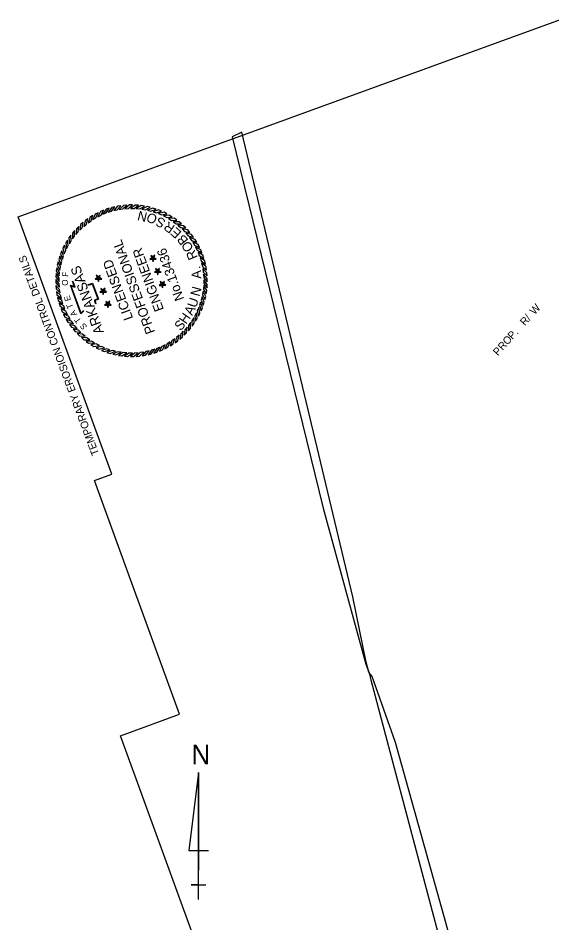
# Model space of a CAD drawing. Extents: x 986289 to 987754, y 1871116 to 1872971.
# Drawn here: x 986289 to 986709, y 1872081 to 1872793 of the extents above; entities that cross this region are included whole.
import ezdxf

# ---------------------------------------------------------------- set-up
doc = ezdxf.new("R2010")
doc.units = 0
for name, color, linetype in [('1', 7, 'Continuous'), ('63', 7, 'Continuous'), ('G-ANNO-SYMB', 7, 'Continuous'), ('NO PLOT', 7, 'Continuous'), ('R_Draft', 7, 'Continuous')]:
    doc.layers.add(name, color=color, linetype=linetype)

msp = doc.modelspace()

# ---------------------------------------------------------------- linework, layer by layer
at = {"layer": '63'}
for p, q in [((986430.69, 1872199.39), (986422.99, 1872137.85)), ((986430.69, 1872099.39), (986430.69, 1872199.39)), ((986430.69, 1872199.39), (986430.69, 1872122.46)), ((986422.99, 1872137.85), (986438.38, 1872137.85)), ((986430.69, 1872099.39), (986430.69, 1872122.46)), ((986430.69, 1872110.93), (986424.92, 1872110.93)), ((986424.92, 1872110.93), (986436.46, 1872110.93)), ((986430.69, 1872099.39), (986430.69, 1872110.93))]:
    msp.add_line(p, q, dxfattribs=at)
at = {"layer": 'G-ANNO-SYMB'}
for points in [[(986351.63, 1872639.84), (986349.35, 1872638.66), (986347.56, 1872634.45), (986349.94, 1872635.87)], [(986355.91, 1872641.74), (986353.54, 1872640.74), (986351.43, 1872636.69), (986353.92, 1872637.91)], [(986360.33, 1872643.29), (986357.89, 1872642.49), (986355.47, 1872638.61), (986358.04, 1872639.64)], [(986364.85, 1872644.5), (986362.36, 1872643.88), (986359.64, 1872640.21), (986362.29, 1872641.03)], [(986369.46, 1872645.34), (986366.93, 1872644.92), (986363.93, 1872641.47), (986366.63, 1872642.09)], [(986374.12, 1872645.82), (986371.57, 1872645.61), (986368.3, 1872642.4), (986371.05, 1872642.8)], [(986378.8, 1872645.94), (986376.24, 1872645.92), (986372.74, 1872642.98), (986375.5, 1872643.17)], [(986383.48, 1872645.68), (986380.92, 1872645.87), (986377.2, 1872643.21), (986379.97, 1872643.18)], [(986388.13, 1872645.06), (986385.59, 1872645.45), (986381.67, 1872643.09), (986384.43, 1872642.84)], [(986392.71, 1872644.08), (986390.21, 1872644.66), (986386.12, 1872642.62), (986388.85, 1872642.15)], [(986397.19, 1872642.74), (986394.75, 1872643.52), (986390.51, 1872641.8), (986393.2, 1872641.12)], [(986401.56, 1872641.05), (986399.19, 1872642.02), (986394.83, 1872640.64), (986397.45, 1872639.76)], [(986405.79, 1872639.03), (986403.5, 1872640.18), (986399.04, 1872639.15), (986401.59, 1872638.06)], [(986339.85, 1872632.23), (986337.91, 1872630.55), (986337.15, 1872626.04), (986339.14, 1872627.97)], [(986343.57, 1872635.07), (986341.5, 1872633.55), (986340.4, 1872629.11), (986342.53, 1872630.89)], [(986347.5, 1872637.62), (986345.33, 1872636.26), (986343.87, 1872631.92), (986346.14, 1872633.53)], [(986409.84, 1872636.68), (986407.65, 1872638), (986403.12, 1872637.33), (986405.58, 1872636.04)], [(986413.7, 1872634.02), (986411.61, 1872635.51), (986407.05, 1872635.19), (986409.4, 1872633.72)], [(986417.33, 1872631.06), (986415.37, 1872632.71), (986410.8, 1872632.75), (986413.02, 1872631.1)], [(986333.13, 1872625.71), (986331.48, 1872623.75), (986331.44, 1872619.17), (986333.09, 1872621.4)], [(986336.36, 1872629.1), (986334.56, 1872627.27), (986334.16, 1872622.72), (986335.99, 1872624.8)], [(986420.72, 1872627.83), (986418.9, 1872629.63), (986414.34, 1872630.03), (986416.43, 1872628.21)], [(986423.85, 1872624.34), (986422.17, 1872626.28), (986417.66, 1872627.04), (986419.6, 1872625.05)], [(986327.51, 1872618.22), (986326.19, 1872616.02), (986326.86, 1872611.5), (986328.15, 1872613.95)], [(986330.17, 1872622.07), (986328.68, 1872619.99), (986329, 1872615.43), (986330.48, 1872617.77)], [(986426.69, 1872620.62), (986425.17, 1872622.69), (986420.74, 1872623.79), (986422.51, 1872621.66)], [(986429.24, 1872616.69), (986427.88, 1872618.87), (986423.55, 1872620.32), (986425.15, 1872618.05)], [(986325.16, 1872614.17), (986324.01, 1872611.87), (986325.04, 1872607.42), (986326.13, 1872609.96)], [(986431.47, 1872612.57), (986430.29, 1872614.84), (986426.08, 1872616.63), (986427.5, 1872614.25)], [(986433.36, 1872608.28), (986432.37, 1872610.65), (986428.31, 1872612.76), (986429.54, 1872610.27)], [(986321.45, 1872605.57), (986320.67, 1872603.13), (986322.39, 1872598.89), (986323.07, 1872601.57)], [(986323.14, 1872609.94), (986322.17, 1872607.56), (986323.55, 1872603.2), (986324.44, 1872605.83)], [(986394.78, 1872604.03), (986393.78, 1872604.32), (986392.22, 1872603.1), (986394.2, 1872603.17)], [(986394.78, 1872604.03), (986394.74, 1872605.08), (986393.1, 1872606.18), (986393.78, 1872604.32)], [(986394.78, 1872604.03), (986394.2, 1872603.17), (986394.87, 1872601.31), (986395.42, 1872603.21)], [(986394.78, 1872604.03), (986395.76, 1872604.39), (986396.3, 1872606.3), (986394.74, 1872605.08)], [(986394.78, 1872604.03), (986395.42, 1872603.21), (986397.4, 1872603.28), (986395.76, 1872604.39)], [(986434.92, 1872603.86), (986434.11, 1872606.3), (986430.23, 1872608.72), (986431.26, 1872606.15)], [(986436.12, 1872599.34), (986435.51, 1872601.83), (986431.83, 1872604.55), (986432.66, 1872601.9)], [(986319.13, 1872596.5), (986318.74, 1872593.97), (986321.1, 1872590.05), (986321.35, 1872592.81)], [(986320.11, 1872601.08), (986319.53, 1872598.58), (986321.57, 1872594.49), (986322.04, 1872597.22)], [(986436.97, 1872594.73), (986436.55, 1872597.26), (986433.1, 1872600.26), (986433.71, 1872597.56)], [(986318.51, 1872591.86), (986318.32, 1872589.3), (986320.98, 1872585.58), (986321.01, 1872588.35)], [(986351.85, 1872588.41), (986351.82, 1872589.45), (986350.17, 1872590.56), (986350.85, 1872588.7)], [(986351.85, 1872588.41), (986352.83, 1872588.77), (986353.38, 1872590.67), (986351.82, 1872589.45)], [(986398.51, 1872593.78), (986397.51, 1872594.07), (986395.95, 1872592.85), (986397.93, 1872592.92)], [(986398.51, 1872593.78), (986398.47, 1872594.82), (986396.83, 1872595.93), (986397.51, 1872594.07)], [(986398.51, 1872593.78), (986397.93, 1872592.92), (986398.61, 1872591.06), (986399.15, 1872592.96)], [(986398.51, 1872593.78), (986399.49, 1872594.14), (986400.04, 1872596.04), (986398.47, 1872594.82)], [(986398.51, 1872593.78), (986399.15, 1872592.96), (986401.13, 1872593.03), (986399.49, 1872594.14)], [(986437.45, 1872590.07), (986437.23, 1872592.63), (986434.02, 1872595.89), (986434.42, 1872593.14)], [(986437.56, 1872585.39), (986437.54, 1872587.95), (986434.6, 1872591.45), (986434.79, 1872588.69)], [(986318.25, 1872587.18), (986318.27, 1872584.62), (986321.21, 1872581.11), (986321.03, 1872583.88)], [(986318.37, 1872582.5), (986318.59, 1872579.94), (986321.79, 1872576.68), (986321.39, 1872579.42)], [(986351.85, 1872588.41), (986350.85, 1872588.7), (986349.29, 1872587.48), (986351.27, 1872587.55)], [(986351.85, 1872588.41), (986351.27, 1872587.55), (986351.95, 1872585.68), (986352.49, 1872587.59)], [(986351.85, 1872588.41), (986352.49, 1872587.59), (986354.47, 1872587.66), (986352.83, 1872588.77)], [(986402.24, 1872583.53), (986401.24, 1872583.82), (986399.68, 1872582.6), (986401.66, 1872582.67)], [(986402.24, 1872583.53), (986402.21, 1872584.57), (986400.56, 1872585.68), (986401.24, 1872583.82)], [(986402.24, 1872583.53), (986401.66, 1872582.67), (986402.34, 1872580.81), (986402.88, 1872582.71)], [(986402.24, 1872583.53), (986403.22, 1872583.89), (986403.77, 1872585.79), (986402.21, 1872584.57)], [(986402.24, 1872583.53), (986402.88, 1872582.71), (986404.86, 1872582.78), (986403.22, 1872583.89)], [(986436.68, 1872576.07), (986437.07, 1872578.6), (986434.71, 1872582.52), (986434.46, 1872579.76)], [(986437.31, 1872580.71), (986437.49, 1872583.27), (986434.83, 1872586.99), (986434.8, 1872584.22)], [(986318.85, 1872577.84), (986319.27, 1872575.31), (986322.72, 1872572.31), (986322.1, 1872575.01)], [(986355.58, 1872578.16), (986354.58, 1872578.45), (986353.02, 1872577.23), (986355, 1872577.3)], [(986355.58, 1872578.16), (986355.55, 1872579.2), (986353.9, 1872580.31), (986354.58, 1872578.45)], [(986355.58, 1872578.16), (986355, 1872577.3), (986355.68, 1872575.43), (986356.22, 1872577.34)], [(986355.58, 1872578.16), (986356.56, 1872578.51), (986357.11, 1872580.42), (986355.55, 1872579.2)], [(986355.58, 1872578.16), (986356.22, 1872577.34), (986358.2, 1872577.41), (986356.56, 1872578.51)], [(986435.7, 1872571.49), (986436.28, 1872573.98), (986434.24, 1872578.08), (986433.78, 1872575.34)], [(986319.69, 1872573.23), (986320.31, 1872570.74), (986323.98, 1872568.02), (986323.16, 1872570.67)], [(986320.9, 1872568.7), (986321.71, 1872566.27), (986325.58, 1872563.85), (986324.55, 1872566.42)], [(986359.31, 1872567.91), (986358.31, 1872568.19), (986356.75, 1872566.97), (986358.73, 1872567.04)], [(986359.31, 1872567.91), (986359.28, 1872568.95), (986357.64, 1872570.06), (986358.31, 1872568.19)], [(986359.31, 1872567.91), (986360.29, 1872568.26), (986360.84, 1872570.17), (986359.28, 1872568.95)], [(986359.31, 1872567.91), (986359.96, 1872567.09), (986361.94, 1872567.16), (986360.29, 1872568.26)], [(986432.68, 1872562.63), (986433.64, 1872565), (986432.27, 1872569.36), (986431.38, 1872566.74)], [(986434.36, 1872567), (986435.14, 1872569.44), (986433.43, 1872573.68), (986432.75, 1872570.99)], [(986322.45, 1872564.29), (986323.45, 1872561.92), (986327.5, 1872559.81), (986326.28, 1872562.29)], [(986359.31, 1872567.91), (986358.73, 1872567.04), (986359.41, 1872565.18), (986359.96, 1872567.09)], [(986428.3, 1872554.35), (986429.63, 1872556.55), (986428.95, 1872561.07), (986427.66, 1872558.61)], [(986430.65, 1872558.4), (986431.8, 1872560.7), (986430.77, 1872565.15), (986429.68, 1872562.6)], [(986324.35, 1872560), (986325.53, 1872557.72), (986329.74, 1872555.94), (986328.32, 1872558.32)], [(986326.58, 1872555.88), (986327.93, 1872553.7), (986332.27, 1872552.25), (986330.66, 1872554.51)], [(986425.64, 1872550.49), (986427.13, 1872552.58), (986426.82, 1872557.14), (986425.34, 1872554.8)], [(986329.12, 1872551.95), (986330.64, 1872549.88), (986335.08, 1872548.78), (986333.3, 1872550.9)], [(986331.96, 1872548.23), (986333.64, 1872546.29), (986338.15, 1872545.53), (986336.22, 1872547.51)], [(986419.45, 1872543.47), (986421.26, 1872545.29), (986421.65, 1872549.85), (986419.83, 1872547.76)], [(986422.68, 1872546.86), (986424.34, 1872548.82), (986424.38, 1872553.39), (986422.72, 1872551.17)], [(986335.09, 1872544.74), (986336.92, 1872542.94), (986341.47, 1872542.54), (986339.39, 1872544.36)], [(986338.48, 1872541.51), (986340.44, 1872539.85), (986345.02, 1872539.81), (986342.79, 1872541.47)], [(986408.31, 1872534.95), (986410.49, 1872536.31), (986411.94, 1872540.64), (986409.68, 1872539.04)], [(986412.24, 1872537.5), (986414.31, 1872539.02), (986415.42, 1872543.45), (986413.29, 1872541.68)], [(986415.97, 1872540.34), (986417.91, 1872542.02), (986418.66, 1872546.53), (986416.68, 1872544.59)], [(986342.12, 1872538.55), (986344.2, 1872537.06), (986348.76, 1872537.38), (986346.42, 1872538.85)], [(986345.97, 1872535.89), (986348.17, 1872534.56), (986352.69, 1872535.24), (986350.24, 1872536.53)], [(986350.03, 1872533.54), (986352.32, 1872532.39), (986356.77, 1872533.42), (986354.23, 1872534.51)], [(986354.25, 1872531.52), (986356.63, 1872530.55), (986360.99, 1872531.92), (986358.36, 1872532.81)], [(986390.96, 1872528.07), (986393.45, 1872528.68), (986396.17, 1872532.36), (986393.52, 1872531.54)], [(986395.49, 1872529.27), (986397.92, 1872530.08), (986400.34, 1872533.96), (986397.77, 1872532.93)], [(986399.91, 1872530.83), (986402.27, 1872531.83), (986404.38, 1872535.88), (986401.9, 1872534.65)], [(986404.19, 1872532.73), (986406.47, 1872533.9), (986408.25, 1872538.11), (986405.87, 1872536.69)], [(986358.62, 1872529.83), (986361.06, 1872529.05), (986365.3, 1872530.76), (986362.62, 1872531.44)], [(986363.11, 1872528.49), (986365.61, 1872527.91), (986369.7, 1872529.95), (986366.97, 1872530.41)], [(986367.69, 1872527.51), (986370.23, 1872527.12), (986374.14, 1872529.48), (986371.38, 1872529.73)], [(986372.33, 1872526.89), (986374.89, 1872526.7), (986378.61, 1872529.36), (986375.84, 1872529.39)], [(986377.01, 1872526.63), (986379.57, 1872526.65), (986383.08, 1872529.59), (986380.31, 1872529.4)], [(986381.69, 1872526.74), (986384.25, 1872526.96), (986387.51, 1872530.17), (986384.77, 1872529.77)], [(986386.35, 1872527.23), (986388.88, 1872527.64), (986391.88, 1872531.09), (986389.18, 1872530.48)]]:
    msp.add_lwpolyline(points, close=True, dxfattribs=at)
for points in [[(986340.49, 1872562.49), (986338.13, 1872560.16), (986329.89, 1872582.76), (986332.95, 1872581.74), (986332.37, 1872583.27), (986331.89, 1872584.54), (986331.56, 1872585.88)], [(986340.22, 1872562.76), (986338.29, 1872560.85), (986330.52, 1872582.15), (986333.59, 1872581.12), (986332.73, 1872583.4), (986332.25, 1872584.66), (986331.93, 1872585.97)], [(986343.31, 1872583.36), (986343.87, 1872583.02), (986344.54, 1872583.08), (986345.81, 1872583.39), (986347.03, 1872583.83), (986351.36, 1872571.93), (986349.61, 1872571.29), (986348.88, 1872571.02), (986348.93, 1872570.12), (986349.53, 1872568.46), (986349.28, 1872568.13)], [(986343.51, 1872583.68), (986343.96, 1872583.41), (986344.48, 1872583.46), (986345.69, 1872583.75), (986347.26, 1872584.32), (986351.85, 1872571.7), (986349.74, 1872570.93), (986349.27, 1872570.76), (986349.3, 1872570.19), (986349.96, 1872568.4), (986349.59, 1872567.9)]]:
    msp.add_lwpolyline(points, dxfattribs=at)
at = {"layer": 'NO PLOT'}
msp.add_lwpolyline([(986774.2, 1871115.6), (986369.23, 1872228.25), (986415.65, 1872245.15), (986348.68, 1872429.14), (986362.4, 1872434.13), (986288.69, 1872636.64), (986718.28, 1872792.99), (986821.23, 1872510.15), (986748.87, 1872483.82), (986894.23, 1872084.45), (986966.59, 1872110.78), (987064.47, 1871841.86), (987008.75, 1871821.58), (987125.95, 1871499.59), (987181.66, 1871519.87), (987263.93, 1871293.85)], close=True, dxfattribs=at)
msp.add_lwpolyline([(986774.2, 1871115.6), (986369.23, 1872228.25), (986415.65, 1872245.15), (986348.68, 1872429.14), (986362.4, 1872434.13), (986288.69, 1872636.64), (986718.28, 1872792.99), (986821.23, 1872510.15), (986748.87, 1872483.82), (986894.23, 1872084.45), (986966.59, 1872110.78), (987064.47, 1871841.86), (987008.75, 1871821.58), (987125.95, 1871499.59), (987181.66, 1871519.87), (987263.93, 1871293.85)], close=True, dxfattribs=at)
msp.add_lwpolyline([(986774.2, 1871115.6), (986369.23, 1872228.25), (986415.65, 1872245.15), (986348.68, 1872429.14), (986362.4, 1872434.13), (986288.69, 1872636.64), (986718.28, 1872792.99), (986821.23, 1872510.15), (986748.87, 1872483.82), (986894.23, 1872084.45), (986966.59, 1872110.78), (987064.47, 1871841.86), (987008.75, 1871821.58), (987125.95, 1871499.59), (987181.66, 1871519.87), (987263.93, 1871293.85)], close=True, dxfattribs=at)
msp.add_lwpolyline([(986774.2, 1871115.6), (986369.23, 1872228.25), (986415.65, 1872245.15), (986348.68, 1872429.14), (986362.4, 1872434.13), (986288.69, 1872636.64), (986718.28, 1872792.99), (986821.23, 1872510.15), (986748.87, 1872483.82), (986894.23, 1872084.45), (986966.59, 1872110.78), (987064.47, 1871841.86), (987008.75, 1871821.58), (987125.95, 1871499.59), (987181.66, 1871519.87), (987263.93, 1871293.85)], close=True, dxfattribs=at)
msp.add_lwpolyline([(986631.76, 1872057.72), (986585.54, 1872222.93), (986567.3, 1872274.81), (986564.8, 1872277.83), (986564.79, 1872277.85), (986564.71, 1872278.16), (986562.57, 1872286.23), (986552.01, 1872337.51), (986464.8, 1872703.09), (986457.01, 1872699.61), (986528.8, 1872407.27), (986562.36, 1872284.62), (986564.8, 1872277.83), (986564.8, 1872277.83), (986564.93, 1872277.37), (986566.25, 1872272.25), (986630.52, 1872029.89)], dxfattribs=at)

# ---------------------------------------------------------------- texts
at = {"layer": '1'}
msp.add_text('TEMPORARY EROSION CONTROL DETAILS', height=6, rotation=110.32307, dxfattribs=at).set_placement((986352.56, 1872450.06))
at = {"layer": '63'}
msp.add_text('N', height=15.38, rotation=360, dxfattribs=at).set_placement((986425.05, 1872205.8))
at = {"layer": 'G-ANNO-SYMB'}
for s, height, rotation, p in [('N', 7.5, 166.10067, (986390.86, 1872639.67)), ('O', 7.5, 154.77573, (986398.99, 1872637.09)), ('S', 7.5, 153.48784, (986405.43, 1872633.95)), ('R', 7.5, 145.65967, (986412.58, 1872629.21)), ('E', 7.5, 137.83149, (986417.86, 1872624.39)), ('PROFESSIONAL', 7.5, 110, (986396.58, 1872545.95)), ('B', 7.5, 128.88501, (986423, 1872618.2)), ('ENGINEER', 7.5, 110, (986403.48, 1872563.67)), ('No.13436', 7.47, 110, (986419.47, 1872572)), ('O', 7.5, 121.42961, (986427.07, 1872611.68)), ('R', 7.5, 113.22866, (986430.15, 1872604.63)), ('ARKANSAS', 7.747, 110, (986356.35, 1872545.85)), ('LICENSED', 7.5, 110, (986379.29, 1872556.76)), ('.', 7.5, 101.30002, (986432.4, 1872595.67)), ('F', 4.75, 85.36282, (986328.12, 1872589.27)), ('A', 7.5, 93.09908, (986432.87, 1872587.99)), ('O', 4.75, 91.2218, (986327.96, 1872582.4)), ('N', 7.5, 74.93262, (986431.29, 1872573.51)), ('E', 4.75, 106.67203, (986330.37, 1872571.02)), ('U', 7.5, 70.90262, (986428.63, 1872564.49)), ('T', 4.75, 111.47887, (986332.31, 1872565.26)), ('A', 4.75, 118.67877, (986335.29, 1872559.82)), ('H', 7.5, 55.61905, (986420.83, 1872551.61)), ('A', 7.5, 63.44722, (986425.63, 1872558.43)), ('T', 4.75, 126.90148, (986338.68, 1872554.92)), ('S', 7.5, 48.16364, (986416.48, 1872546.39)), ('S', 4.75, 129.77256, (986343.29, 1872550.18))]:
    msp.add_text(s, height=height, rotation=rotation, dxfattribs=at).set_placement(p)
at = {"layer": 'R_Draft'}
for s, p in [('W', (986695.08, 1872559.07)), ('R', (986687.39, 1872550.49)), ('/', (986691.17, 1872554.71)), ('P', (986677.64, 1872539.63)), ('O', (986673.73, 1872535.27)), ('.', (986681.42, 1872543.85)), ('P', (986666.15, 1872526.83)), ('R', (986669.94, 1872531.05))]:
    msp.add_text(s, height=6, rotation=48.10538, dxfattribs=at).set_placement(p)

doc.saveas('drawing.dxf')
